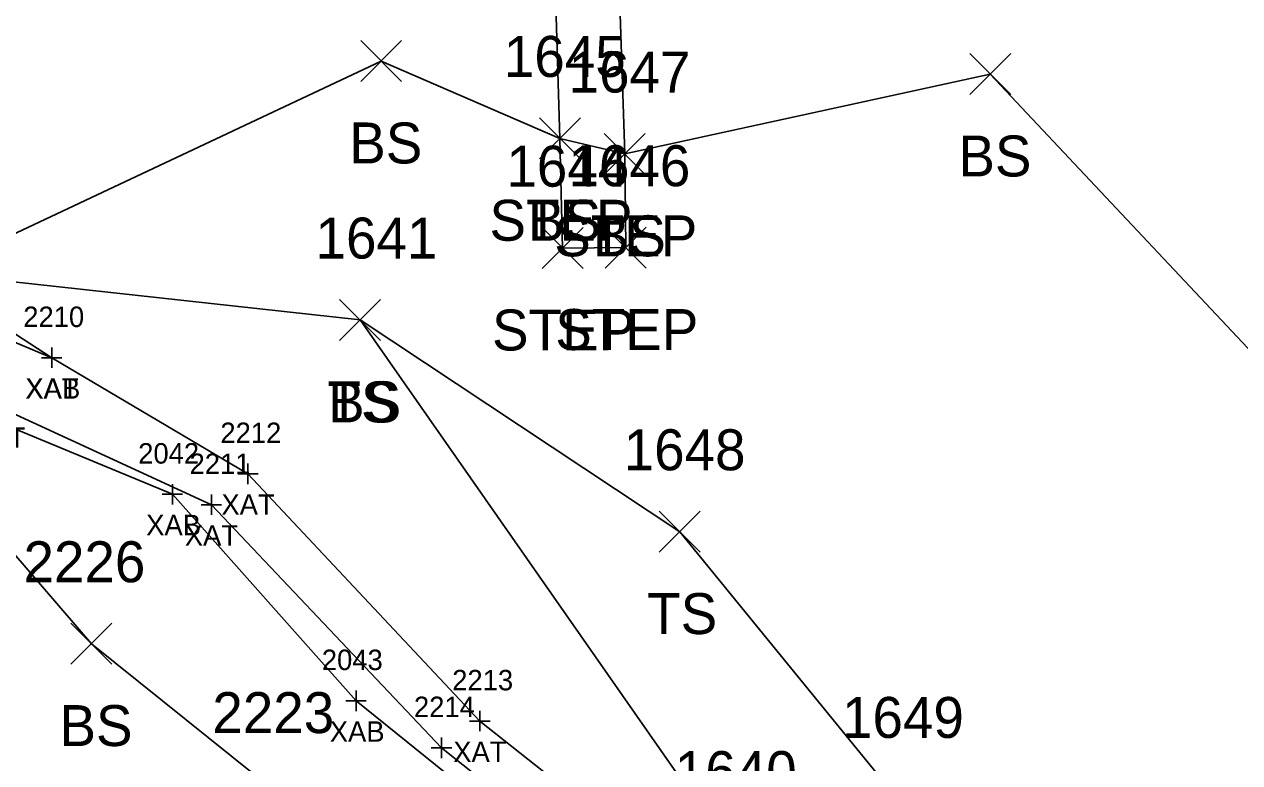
# Model space of a CAD drawing. Extents: x 1647133 to 1649138, y 411736 to 414924.
# Drawn here: x 1649009.1 to 1649068.5, y 412180 to 412216.1 of the extents above; entities that cross this region are included whole.
import ezdxf

# ---------------------------------------------------------------- set-up
doc = ezdxf.new("R2010")
doc.units = 0
for name, color, linetype in [('B_A', 7, 'Continuous'), ('B_I', 7, 'Continuous'), ('B_TIC', 7, 'Continuous'), ('BSUBM', 7, 'Continuous'), ('L_A', 7, 'Continuous'), ('L_I', 7, 'Continuous'), ('L_TIC', 7, 'Continuous'), ('LBF', 7, 'Continuous'), ('LELB', 7, 'Continuous')]:
    doc.layers.add(name, color=color, linetype=linetype)

msp = doc.modelspace()

# ---------------------------------------------------------------- linework, layer by layer
at = {"layer": 'B_TIC'}
for p, q in [((1649010.46, 412199.768), (1649010.535, 412199.768)), ((1649010.46, 412199.768), (1649010.535, 412199.768)), ((1649020.039, 412194.102), (1649020.115, 412194.102)), ((1649016.351, 412193.098), (1649016.427, 412193.098)), ((1649018.253, 412192.591), (1649018.328, 412192.591)), ((1649025.316, 412183.014), (1649025.391, 412183.014)), ((1649031.359, 412182.024), (1649031.435, 412182.024)), ((1649029.491, 412180.719), (1649029.567, 412180.719))]:
    msp.add_line(p, q, dxfattribs=at)
for points in [[(1649010.456, 412199.268), (1649010.456, 412200.268)], [(1649010.456, 412199.268), (1649010.456, 412200.268)], [(1649009.956, 412199.768), (1649010.956, 412199.768)], [(1649009.956, 412199.768), (1649010.956, 412199.768)], [(1649020.036, 412193.602), (1649020.036, 412194.602)], [(1649019.536, 412194.102), (1649020.536, 412194.102)], [(1649016.348, 412192.598), (1649016.348, 412193.598)], [(1649015.848, 412193.098), (1649016.848, 412193.098)], [(1649018.249, 412192.091), (1649018.249, 412193.091)], [(1649017.749, 412192.591), (1649018.749, 412192.591)], [(1649025.312, 412182.514), (1649025.312, 412183.514)], [(1649024.812, 412183.014), (1649025.812, 412183.014)], [(1649031.356, 412181.524), (1649031.356, 412182.524)], [(1649030.856, 412182.024), (1649031.856, 412182.024)], [(1649029.488, 412180.219), (1649029.488, 412181.219)], [(1649028.988, 412180.719), (1649029.988, 412180.719)]]:
    msp.add_lwpolyline(points, dxfattribs=at)
at = {"layer": 'BSUBM'}
for points in [[(1648980.212, 412272.224), (1648969.681, 412271.317), (1648969.261, 412266.421), (1648968.934, 412254.381), (1648969.053, 412251.503), (1648969.525, 412251.264), (1648969.788, 412227.697), (1648987.092, 412207.478), (1648990.118, 412205.514), (1649004.163, 412198.216), (1649004.665, 412197.942), (1649016.348, 412193.098), (1649025.312, 412183.014), (1649046.031, 412166.296)], [(1648999.252, 412222.01), (1649000.017, 412221.012), (1648993.191, 412215.427), (1648991.492, 412213.898), (1648995.274, 412209.174), (1649004.473, 412203.654), (1649010.456, 412199.768)], [(1648988.03, 412209.126), (1648991.506, 412213.009), (1648996.391, 412206.994), (1649003.26, 412202.795), (1649010.456, 412199.768), (1649020.036, 412194.102), (1649031.356, 412182.024), (1649047.922, 412168.893)], [(1648988.03, 412209.126), (1648994.262, 412203.891), (1649001.042, 412200.278), (1649007.864, 412197.371), (1649018.249, 412192.591), (1649029.488, 412180.719), (1649045.657, 412167.83), (1649047.922, 412168.893)]]:
    msp.add_lwpolyline(points, dxfattribs=at)
at = {"layer": 'L_TIC'}
for points in [[(1649025.54, 412213.258), (1649027.54, 412215.258)], [(1649027.54, 412213.258), (1649025.54, 412215.258)], [(1649055.28, 412212.622), (1649057.28, 412214.622)], [(1649057.28, 412212.622), (1649055.28, 412214.622)], [(1649034.268, 412209.483), (1649036.268, 412211.483)], [(1649036.268, 412209.483), (1649034.268, 412211.483)], [(1649034.268, 412209.483), (1649036.268, 412211.483)], [(1649036.268, 412209.483), (1649034.268, 412211.483)], [(1649037.43, 412208.721), (1649039.43, 412210.721)], [(1649039.43, 412208.721), (1649037.43, 412210.721)], [(1649037.43, 412208.721), (1649039.43, 412210.721)], [(1649039.43, 412208.721), (1649037.43, 412210.721)], [(1649034.394, 412204.124), (1649036.394, 412206.124)], [(1649036.394, 412204.124), (1649034.394, 412206.124)], [(1649034.394, 412204.124), (1649036.394, 412206.124)], [(1649036.394, 412204.124), (1649034.394, 412206.124)], [(1649037.481, 412204.146), (1649039.481, 412206.146)], [(1649039.481, 412204.146), (1649037.481, 412206.146)], [(1649024.511, 412200.612), (1649026.511, 412202.612)], [(1649026.511, 412200.612), (1649024.511, 412202.612)], [(1649024.511, 412200.612), (1649026.511, 412202.612)], [(1649026.511, 412200.612), (1649024.511, 412202.612)], [(1649040.119, 412190.273), (1649042.119, 412192.273)], [(1649042.119, 412190.273), (1649040.119, 412192.273)], [(1649011.393, 412184.804), (1649013.393, 412186.804)], [(1649013.393, 412184.804), (1649011.393, 412186.804)]]:
    msp.add_lwpolyline(points, dxfattribs=at)
at = {"layer": 'LBF'}
for points in [[(1649035.394, 412205.124), (1649035.268, 412210.483), (1649034.74, 412227.846), (1649032.165, 412233.292), (1649030.965, 412236.013), (1649033.671, 412237.119)], [(1649035.394, 412205.124), (1649038.481, 412205.146), (1649038.43, 412209.721), (1649037.817, 412228.224), (1649036.041, 412232.414), (1649033.671, 412237.119)]]:
    msp.add_lwpolyline(points, dxfattribs=at)
at = {"layer": 'LELB'}
for points in [[(1649076.641, 412139.604), (1649064.069, 412155.759), (1649043.704, 412175.556), (1649025.511, 412201.612), (1649004.571, 412203.917), (1649026.54, 412214.258), (1649035.268, 412210.483), (1649038.43, 412209.721), (1649056.28, 412213.622), (1649076.026, 412192.594), (1649101.777, 412169.939)], [(1649025.511, 412201.612), (1649041.119, 412191.273), (1649051.787, 412178.201), (1649085.094, 412147.879)], [(1649055.656, 412117.815), (1649039.256, 412150.575), (1649031.138, 412167.605), (1649021.557, 412178.437), (1649012.393, 412185.804), (1649004.61, 412194.853)]]:
    msp.add_lwpolyline(points, dxfattribs=at)

# ---------------------------------------------------------------- texts
at = {"layer": 'B_A'}
for s, p in [('XAT', (1649009.161, 412197.768)), ('XAB', (1649009.177, 412197.768)), ('XAT', (1649006.568, 412195.371)), ('XAT', (1649018.741, 412192.102)), ('XAB', (1649015.068, 412191.098)), ('XAT', (1649016.954, 412190.591)), ('XAB', (1649024.033, 412181.014)), ('XAT', (1649030.061, 412180.024))]:
    msp.add_text(s, height=1, dxfattribs=at).set_placement(p)
at = {"layer": 'B_I'}
for s, p in [('2210', (1649009.066, 412201.268)), ('2210', (1649009.066, 412201.268)), ('2212', (1649018.689, 412195.602)), ('2042', (1649014.678, 412194.598)), ('2211', (1649017.186, 412194.091)), ('2043', (1649023.643, 412184.514)), ('2213', (1649030.009, 412183.524)), ('2214', (1649028.141, 412182.219))]:
    msp.add_text(s, height=1, dxfattribs=at).set_placement(p)
at = {"layer": 'L_A'}
for s, p in [('BS', (1649024.981, 412209.258)), ('BS', (1649054.721, 412208.622)), ('STEP', (1649031.827, 412205.483)), ('BS', (1649033.709, 412205.483)), ('STEP', (1649034.989, 412204.721)), ('BS', (1649036.871, 412204.721)), ('STEP', (1649031.953, 412200.124)), ('STEP', (1649031.953, 412200.124)), ('STEP', (1649035.04, 412200.146)), ('TS', (1649023.92, 412196.612)), ('BS', (1649023.952, 412196.612)), ('TS', (1649039.528, 412186.273)), ('BS', (1649010.834, 412180.804))]:
    msp.add_text(s, height=2, dxfattribs=at).set_placement(p)
at = {"layer": 'L_I'}
for s, p in [('1645', (1649032.528, 412213.483)), ('1645', (1649032.528, 412213.483)), ('1647', (1649035.69, 412212.721)), ('1647', (1649035.69, 412212.721)), ('1644', (1649032.654, 412208.124)), ('1644', (1649032.654, 412208.124)), ('1646', (1649035.686, 412208.146)), ('1641', (1649023.337, 412204.612)), ('1641', (1649023.337, 412204.612)), ('1648', (1649038.379, 412194.273)), ('2226', (1649009.078, 412188.804)), ('2223', (1649018.298, 412181.437)), ('1649', (1649049.039, 412181.201)), ('1640', (1649040.877, 412178.556))]:
    msp.add_text(s, height=2, dxfattribs=at).set_placement(p)

doc.saveas('drawing.dxf')
